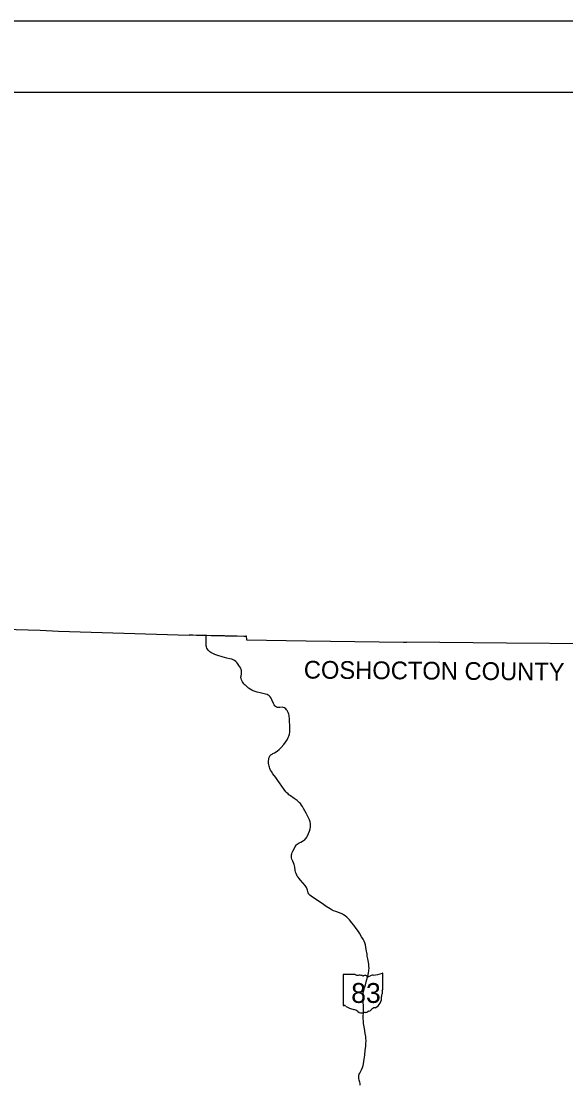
# Model space of a CAD drawing. Extents: x 2004415 to 2276415, y 751181 to 927181.
# Drawn here: x 2124487 to 2155196, y 867212 to 927181 of the extents above; entities that cross this region are included whole.
import ezdxf

# ---------------------------------------------------------------- set-up
doc = ezdxf.new("R2010")
doc.units = 0
for name, color, linetype in [('GM_X_County', 7, 'Continuous'), ('GM_X_County_Text', 7, 'Continuous'), ('GM_X_State_Route', 7, 'Continuous'), ('GM_X_State_Shield', 7, 'Continuous'), ('SH_Border', 7, 'Continuous'), ('SH_Cut_Line', 7, 'Continuous')]:
    doc.layers.add(name, color=color, linetype=linetype)

msp = doc.modelspace()

# ---------------------------------------------------------------- linework, layer by layer
at = {"layer": 'GM_X_County'}
msp.add_lwpolyline([(2122132, 892938), (2125547, 892838), (2126585, 892786), (2133951, 892571), (2133956, 892572), (2133965, 892574), (2133971, 892575), (2133978, 892576), (2133984, 892576), (2133992, 892577), (2134003, 892576), (2134090, 892576), (2134158, 892574), (2134373, 892570), (2134751, 892558), (2134916, 892555), (2134951, 892554), (2135202, 892549), (2135323, 892546), (2135463, 892544), (2135510, 892543), (2135606, 892542), (2135654, 892541), (2135717, 892540), (2135760, 892539), (2135871, 892537), (2135937, 892535), (2135985, 892533), (2136113, 892530), (2136193, 892528), (2136275, 892528), (2136373, 892525), (2136668, 892518), (2137044, 892505), (2137101, 892504), (2137123, 892504), (2137135, 892506), (2137144, 892509), (2137152, 892512), (2137161, 892516), (2137167, 892519), (2137174, 892523), (2137184, 892297), (2140547, 892239), (2146047, 892160), (2146063, 892162), (2146077, 892162), (2146095, 892162), (2146113, 892162), (2146146, 892162), (2146163, 892162), (2146180, 892164), (2146195, 892168), (2146209, 892175), (2146221, 892185), (2151850, 892125), (2156726, 892101)], dxfattribs=at)
at = {"layer": 'GM_X_State_Route'}
for points in [[(2135060, 891687), (2135025, 891726), (2134988, 891781), (2134959, 891835), (2134935, 891900), (2134921, 891955), (2134913, 892010), (2134907, 892062), (2134907, 892122), (2134907, 892258), (2134917, 892552)], [(2137112, 889749), (2137048, 889817), (2136962, 889938), (2136910, 890035), (2136885, 890113), (2136880, 890160), (2136880, 890201), (2136885, 890253), (2136908, 890374), (2136917, 890448), (2136917, 890508), (2136912, 890565), (2136894, 890628), (2136864, 890701), (2136767, 890854), (2136707, 890940), (2136649, 891018), (2136587, 891080), (2136510, 891138), (2136444, 891172), (2136358, 891202), (2136250, 891231), (2136079, 891269), (2135947, 891304), (2135825, 891341), (2135577, 891424), (2135411, 891481), (2135260, 891546), (2135187, 891583), (2135127, 891624), (2135063, 891683), (2135060, 891687)], [(2139730, 880073), (2139731, 880119), (2139737, 880178), (2139753, 880240), (2139775, 880305), (2139812, 880383), (2139876, 880523), (2139943, 880653), (2140003, 880735), (2140047, 880781), (2140104, 880823), (2140163, 880855), (2140246, 880895), (2140348, 880944), (2140409, 880980), (2140473, 881026), (2140521, 881073), (2140555, 881119), (2140592, 881172), (2140625, 881239), (2140688, 881382), (2140736, 881504), (2140782, 881635), (2140800, 881713), (2140808, 881785), (2140808, 881862), (2140807, 881931), (2140782, 882032), (2140736, 882153), (2140549, 882520), (2140407, 882797), (2140356, 882893), (2140295, 882984), (2140230, 883066), (2140187, 883114), (2140113, 883184), (2140042, 883240), (2139879, 883358), (2139666, 883500), (2139623, 883533), (2139582, 883565), (2139532, 883607), (2139474, 883663), (2139411, 883736), (2139311, 883869), (2139048, 884243), (2138963, 884364), (2138842, 884531), (2138685, 884752), (2138600, 884874), (2138550, 884957), (2138512, 885047), (2138484, 885126), (2138465, 885185), (2138451, 885256), (2138439, 885339), (2138433, 885389), (2138434, 885484), (2138442, 885556), (2138458, 885634), (2138491, 885710), (2138514, 885752), (2138565, 885814), (2138633, 885861), (2138684, 885889), (2138768, 885929), (2138866, 885980), (2138942, 886033), (2139036, 886111), (2139151, 886224), (2139292, 886392), (2139394, 886527), (2139481, 886663), (2139540, 886784), (2139573, 886869), (2139609, 886988), (2139631, 887097), (2139641, 887204), (2139637, 887417), (2139624, 887752), (2139616, 887879), (2139605, 887962), (2139593, 888035), (2139571, 888117), (2139540, 888200), (2139491, 888306), (2139455, 888358), (2139402, 888415), (2139335, 888460), (2139267, 888487), (2139195, 888499), (2139079, 888488), (2138998, 888482), (2138941, 888488), (2138889, 888505), (2138830, 888541), (2138782, 888585), (2138751, 888634), (2138713, 888715), (2138627, 888909), (2138581, 889003), (2138529, 889078), (2138470, 889138), (2138420, 889176), (2138362, 889209), (2138264, 889242), (2137958, 889312), (2137786, 889352), (2137674, 889382), (2137568, 889425), (2137485, 889466), (2137396, 889515), (2137299, 889580), (2137243, 889626), (2137126, 889734), (2137112, 889749)], [(2143608, 867187), (2143596, 867272), (2143579, 867361), (2143548, 867476), (2143526, 867585), (2143518, 867648), (2143523, 867703), (2143532, 867751), (2143554, 867812), (2143581, 867873), (2143674, 868052), (2143740, 868191), (2143771, 868292), (2143794, 868386), (2143836, 868649), (2143863, 868887), (2143891, 869153), (2143915, 869359), (2143927, 869527), (2143936, 869699), (2143929, 869820), (2143913, 869931), (2143884, 870108), (2143837, 870385), (2143796, 870658), (2143783, 870799), (2143778, 870948), (2143781, 871392), (2143783, 871634), (2143778, 871884), (2143770, 872085), (2143764, 872213), (2143766, 872286), (2143772, 872369), (2143791, 872466), (2143808, 872533), (2143846, 872668), (2143896, 872851), (2143938, 873006), (2144046, 873400), (2144075, 873534), (2144091, 873612), (2144100, 873695), (2144103, 873771), (2144096, 873896), (2144082, 874018), (2144032, 874320), (2144006, 874469), (2143990, 874579), (2143949, 874831), (2143925, 874976), (2143898, 875109), (2143865, 875222), (2143827, 875310), (2143769, 875423), (2143684, 875560), (2143564, 875750), (2143501, 875849), (2143383, 876025), (2143241, 876203), (2143119, 876355), (2143071, 876418), (2142992, 876514), (2142912, 876607), (2142849, 876666), (2142762, 876736), (2142666, 876800), (2142604, 876833), (2142526, 876870), (2142383, 876924), (2142233, 876975), (2142101, 877024), (2142016, 877064), (2141903, 877130), (2141692, 877270), (2141452, 877433), (2140977, 877748), (2140837, 877843), (2140765, 877900), (2140724, 877946), (2140705, 877974), (2140675, 878033), (2140653, 878105), (2140637, 878179), (2140615, 878243), (2140578, 878332), (2140507, 878446), (2140240, 878753), (2140162, 878842), (2140102, 878914), (2140057, 878978), (2140024, 879032), (2139986, 879120), (2139962, 879205), (2139945, 879304), (2139918, 879484), (2139906, 879561), (2139884, 879639), (2139802, 879828), (2139754, 879940), (2139732, 880014), (2139730, 880073)]]:
    msp.add_lwpolyline(points, dxfattribs=at)
at = {"layer": 'GM_X_State_Shield'}
for p, q in [((2142641, 873406), (2142641, 871705)), ((2143319, 873435), (2142663, 873435)), ((2144882, 872588), (2144882, 873478)), ((2144882, 872588), (2144882, 872588))]:
    msp.add_line(p, q, dxfattribs=at)
for centre, radius, start, end in [((2142666, 873410), 26, 98.1301, 188.1301), ((2143476, 873633), 252, 231.61951, 271.11188), ((2143559, 872480), 904, 80.48669, 94.98827), ((2143764, 873419), 72.7, 219.79206, 297.10237), ((2143871, 873222), 151, 54.46668, 119.14113), ((2144066, 873492), 182, 233.85621, 294.82819), ((2144387, 872916), 478, 97.34618, 120.76885), ((2144084, 875755), 2377, 275.84447, 288.90645), ((2144857, 873481), 25, 351.86209, 97.738), ((2144876, 872522), 38.6, 107.94398, 210.33697), ((2144856, 872584), 26.7, 289.60381, 7.73413), ((2144217, 872102), 595, 292.30889, 8.98584), ((2144972, 872215), 169, 136.8065, 186.92959), ((2144631, 872410), 232, 340.03296, 23.64957), ((2142667, 871701), 26.2, 171.95839, 258.30661), ((2142671, 871875), 200, 267.33899, 280.60386), ((2142712, 871607), 72.1, 29.74838, 93.27175), ((2143622, 873135), 1716, 240.41292, 257.1985), ((2143110, 870941), 537, 47.18416, 75.83597), ((2144077, 871306), 51.1, 65.75173, 132.64842), ((2144055, 871540), 192, 282.87319, 323.27711), ((2144468, 871227), 326, 94.40312, 142.57675), ((2143691, 871598), 341, 230.70037, 286.29184), ((2143888, 871010), 280, 85.69512, 111.20995), ((2143913, 871471), 182, 268.77702, 315.54927)]:
    msp.add_arc(centre, radius, start, end, dxfattribs=at)
at = {"layer": 'SH_Border'}
msp.add_lwpolyline([(2016415, 923181), (2272415, 923181), (2272415, 755181), (2016415, 755181)], close=True, dxfattribs=at)
at = {"layer": 'SH_Cut_Line'}
msp.add_lwpolyline([(2004415, 751181), (2276415, 751181), (2276415, 927181), (2004415, 927181)], close=True, dxfattribs=at)

# ---------------------------------------------------------------- texts
at = {"layer": 'GM_X_County_Text'}
msp.add_text('COSHOCTON COUNTY', height=1000, rotation=359.54831, dxfattribs=at).set_placement((2140421, 890117))
at = {"layer": 'GM_X_State_Shield'}
msp.add_text('83', height=1120.7, dxfattribs=at).set_placement((2143097, 871825))

doc.saveas('drawing.dxf')
